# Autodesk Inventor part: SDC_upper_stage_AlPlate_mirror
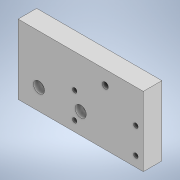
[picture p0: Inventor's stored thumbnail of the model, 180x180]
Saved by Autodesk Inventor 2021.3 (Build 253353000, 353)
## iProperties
Created: 2022-02
Part Number: SDC_upper_stage_AlPlate_mirror
Material: 一般
Document SubType Name: Modeling
Designer: kengo
Density: 1 g/cm^3
Appearance: 既定
Author: kengo
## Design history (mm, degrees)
derived "SDC_upper_stage_AlPlate.ipt"
feature "ソリッド1::SDC_upper_stage_AlPlate.ipt" dims "d0" = 10
tag "TaggingFeature1"
node "ソリッド1"
